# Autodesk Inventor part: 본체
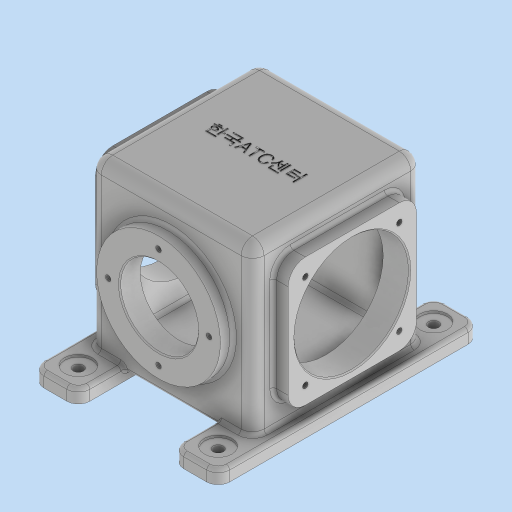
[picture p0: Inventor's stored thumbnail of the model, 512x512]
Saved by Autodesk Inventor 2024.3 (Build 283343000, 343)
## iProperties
Created: 2026-01
Part Number: 본체
Material: 일반
Document SubType Name: Modeling
Designer: PC2-02
Density: 1 g/cm^3
Appearance: 기본값
Author: PC2-02
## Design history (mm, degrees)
sketch "스케치1"
  geometry: L1 (-81, 114)-(81, 114); L2 (81, 114)-(81, -114); L3 (81, -114)-(-81, -114); L4 (-81, -114)-(-81, 114); 1 further point
  constraints: 8 end point, 2 parallel, 1 horizontal, 1 perpendicular
  dimensions: "d0" = 162 distance between parallel lines of L2 L4; "d1" = 81 distance from line of point (0, 0) L4; "d2" = 228 distance between parallel lines of L3 L1; "d3" = 114 distance from line of point (0, 0) L1
extrude "돌출1" new body sketch "스케치1" distance "d4" = 12; taper "d5" = 0 deg
sketch "스케치12"
  geometry: L1 (81, 114)-(-81, 114) reference; L2 (-81, -114)-(81, -114) reference; L3 (-41, 114)-(41, 114); L4 (41, 114)-(41, -114); L5 (41, -114)-(-41, -114); L6 (-41, -114)-(-41, 114); L7 (81, -114)-(81, 114) reference; L8 (-81, 114)-(-81, -114) reference; 3 further points
  constraints: 8 end point, 2 parallel, 2 point on line, 1 horizontal, 1 perpendicular
  dimensions: "d91" = 40 distance between parallel lines of L7 L4; "d92" = 40 distance between parallel lines of L8 L6
extrude "돌출7" cut sketch "스케치12" extent not by distance; stored distance "d93" = 0; taper "d94" = 0 deg
sketch "스케치2"
  geometry: L1 (71, 156)-(-71, 156); L2 (-71, 156)-(-71, 8); L3 (-71, 8)-(71, 8); L4 (71, 8)-(71, 156); L5 (81, 0)-(-81, 0) reference; 2 further points
  constraints: 8 end point, 2 parallel, 1 horizontal, 1 midpoint, 1 perpendicular
  dimensions: "d6" = 156 distance between parallel lines of L5 L1; "d7" = 142 distance between parallel lines of L2 L4; "d8" = 71 distance from line of point (0, 0) L4; "d90" = 8 distance between parallel lines of L5 L3
extrude "돌출2" join sketch "스케치2" stored distance "d9" = 148; taper "d10" = 0 deg
sketch "스케치3"
  geometry: L1 (-56, 140)-(56, 140); L2 (56, 140)-(56, 28); L3 (56, 28)-(-56, 28); L4 (-56, 28)-(-56, 140); L5 (-74, 156)-(-74, 12) reference; 2 further points
  constraints: 8 end point, 2 parallel, 1 horizontal, 1 midpoint, 1 perpendicular
  dimensions: "d11" = 112 distance between parallel lines of L2 L4; "d12" = 56 distance from line of point (0, 0) L4; "d13" = 112 distance between parallel lines of L3 L1; "d14" = 56 distance from line of point (-74, 84) L1
extrude "돌출3" join sketch "스케치3" stored distance "d15" = 168; taper "d16" = 0 deg
sketch "스케치4"
  geometry: L1 (-81, 0)-(81, 0) reference; C1 r 54 at (0, 82); 2 further points
  constraints: 1 centre point, 1 midpoint, 1 vertical alignment
  dimensions: "d17" = 108 diameter of C1; "d18" = 82 distance from line of L1 C1.centre
extrude "돌출4" join sketch "스케치4" distance "d19" = 11; taper "d20" = 0 deg
sketch "스케치6"
  geometry: L1 (-28, 56)-(-140, 56) reference; L2 (-140, 56)-(-140, -56) reference; 2 further points
  dimensions: "d25" = 56 distance from line of L1 point (-84, 0); "d26" = 56 distance from line of point (-84, 0) L2
hole "구멍1" sketch "스케치6" at (-84, 0) diameter "d27" = 100; stored, may be unused: countersink angle "d31" = 90 deg, drill point angle "d33" = 118 deg; dims "d28" = 6, "d29" = 4, "d30" = 2, "d32" = 8
sketch "스케치7"
  geometry: C1 r 54 at (0, 0) reference; 2 further points
  constraints: 1 coincident
hole "구멍2" sketch "스케치7" at (0, 0) diameter "d34" = 68; stored, may be unused: countersink angle "d38" = 90 deg, drill point angle "d40" = 118 deg; dims "d35" = 6, "d36" = 4, "d37" = 2, "d39" = 8
sketch "스케치8"
  geometry: L1 (-67, 149)-(67, 149); L2 (67, 149)-(67, 15); L3 (67, 15)-(-67, 15); L4 (-67, 15)-(-67, 149); L5 (74, 12)-(74, 156) reference; L6 (-74, 156)-(74, 156) reference; L7 (-74, 156)-(-74, 12) reference; L8 (74, 12)-(114, 12) reference; L9 (74, 8)-(-74, 8) reference; 1 further point
  constraints: 8 end point, 2 parallel, 1 horizontal, 1 perpendicular
  dimensions: "d41" = 7 distance between parallel lines of L5 L2; "d42" = 7 distance between parallel lines of L6 L1; "d44" = 7 distance between parallel lines of L4 L7; "d111" = 7 distance between parallel lines of L9 L3
extrude "돌출6" cut sketch "스케치8" stored distance "d45" = 122; taper "d46" = 0 deg
sketch "스케치9"
  geometry: 2 further points
  dimensions: "d47" = 61 horizontal distance of point (61, 94) point (0, 0); "d48" = 94 vertical distance of point (0, 0) point (61, 94)
hole "구멍3" sketch "스케치9" at (61, 94) diameter "d49" = 9; stored, may be unused: countersink angle "d53" = 90 deg, drill point angle "d55" = 118 deg; dims "d50" = 6, "d51" = 24, "d52" = 2, "d54" = 8
sketch "스케치10" dims "d62" = 88
  geometry: C1 r 54 at (0, 0) reference; 3 further points
  constraints: 2 vertical alignment, 3 other
hole "구멍4" sketch "스케치10" at (0, 44) diameter "d63" = 4.917; stored, may be unused: countersink angle "d67" = 90 deg, drill point angle "d69" = 118 deg; dims "d64" = 12, "d65" = 4, "d66" = 2, "d68" = 14
sketch "스케치11"
  geometry: C1 r 50 at (-84, 0) reference; 2 further points
  dimensions: "d73" = 41 vertical distance of point (-125, 41) point (0, 0); "d74" = 41 horizontal distance of C1.centre point (-125, 41)
hole "구멍5" sketch "스케치11" at (-125, 41) diameter "d75" = 4.917; stored, may be unused: countersink angle "d79" = 90 deg, drill point angle "d81" = 118 deg; dims "d76" = 12, "d77" = 4, "d78" = 2, "d80" = 14
fillet "모깎기1" dims "d88" = 10
fillet "모깎기2" dims "d89" = 10
fillet "모깎기9" dims "d109" = 3
fillet "모깎기10" dims "d110" = 3
fillet "모깎기3" dims "d96" = 3
fillet "모깎기5" dims "d98" = 15
fillet "모깎기6" dims "d99" = 3
fillet "모깎기7" dims "d100" = 3
fillet "모깎기8" dims "d101" = 3
chamfer "모따기1" distance "d102" = 1; stored, may be unused: second distance "d103" = 2, angle "d104" = 45 deg
sketch "스케치13"
  geometry: L1 (16, 70.5)-(106, 70.5); L2 (106, 70.5)-(106, 57.5); L3 (106, 57.5)-(16, 57.5); L4 (16, 57.5)-(16, 70.5); L5 (16, 64)-(106, 64); L6 (61, 70.5)-(61, 57.5); 2 further points
  constraints: 5 midpoint, 4 end point, 1 coincident, 1 vertical, 2 other
  dimensions: "d105" = 13 distance between parallel lines of L1 L3; "d106" = 90 distance between parallel lines of L4 L2
feature "엠보싱1" sketch "스케치13" dims "d0" = 162, "d1" = 81, "d2" = 228, "d3" = 114, "d107" = 0.5, "d108" = 0
feature "̾耀̀耀͂耀̈́耀͆耀͈耀͊耀͌耀" dims "d0" = 162, "d1" = 81, "d2" = 228, "d3" = 114, "d4" = 12, "d5" = 0, "d6" = 156, "d7" = 142, "d8" = 71, "d9" = 148, "d10" = 0, "d11" = 112, "d12" = 56, "d13" = 112, "d14" = 56, "d15" = 168, "d16" = 0, "d17" = 108, "d18" = 82, "d19" = 11, "d20" = 0, "d25" = 56, "d26" = 56, "d27" = 100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
node "솔리드1"
pattern_linear "직사각형 패턴1" dims "d58" = 188, "d61" = 122
pattern_circular "원형 패턴1" dims angle "d71" = 360 deg
pattern_linear "직사각형 패턴2" dims "d84" = 82, "d87" = 82
mirror "미러1"
feature "A9D066F2-1C7D-4E18-AEED-F7BC21143FA4" dims "d49" = 9, "d50" = 6, "d51" = 24, "d52" = 2, "d53" = 90 deg, "d54" = 8, "d55" = 118 deg
